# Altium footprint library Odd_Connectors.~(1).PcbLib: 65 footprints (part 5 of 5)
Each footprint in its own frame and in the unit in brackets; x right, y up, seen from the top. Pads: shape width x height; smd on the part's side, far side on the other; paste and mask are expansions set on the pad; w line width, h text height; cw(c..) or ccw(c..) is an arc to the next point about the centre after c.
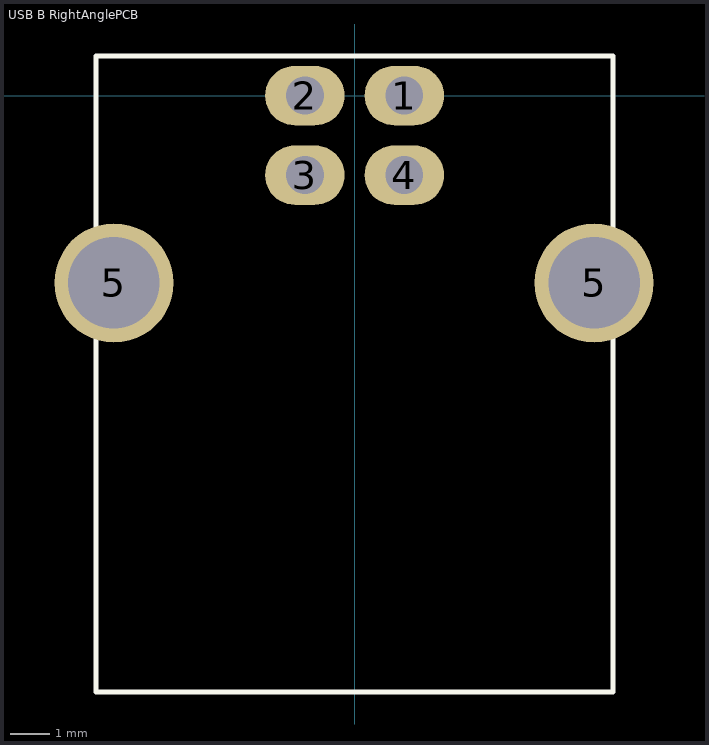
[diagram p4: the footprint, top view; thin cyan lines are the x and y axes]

## USB B RightAnglePCB [mm]
height 11.5
pads (6):
  oval 2x1.5 hole 0.95: 1(1.25,0) 2(-1.25,0) 3(-1.25,-2) 4(1.25,-2)
  round 3 hole 2.3: 5(-6.05,-4.71) 5(6.02,-4.71)
Top Overlay:
  lines w0.127: -6.5,-15 6.5,-15 6.5,1 -6.5,1 -6.5,-15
